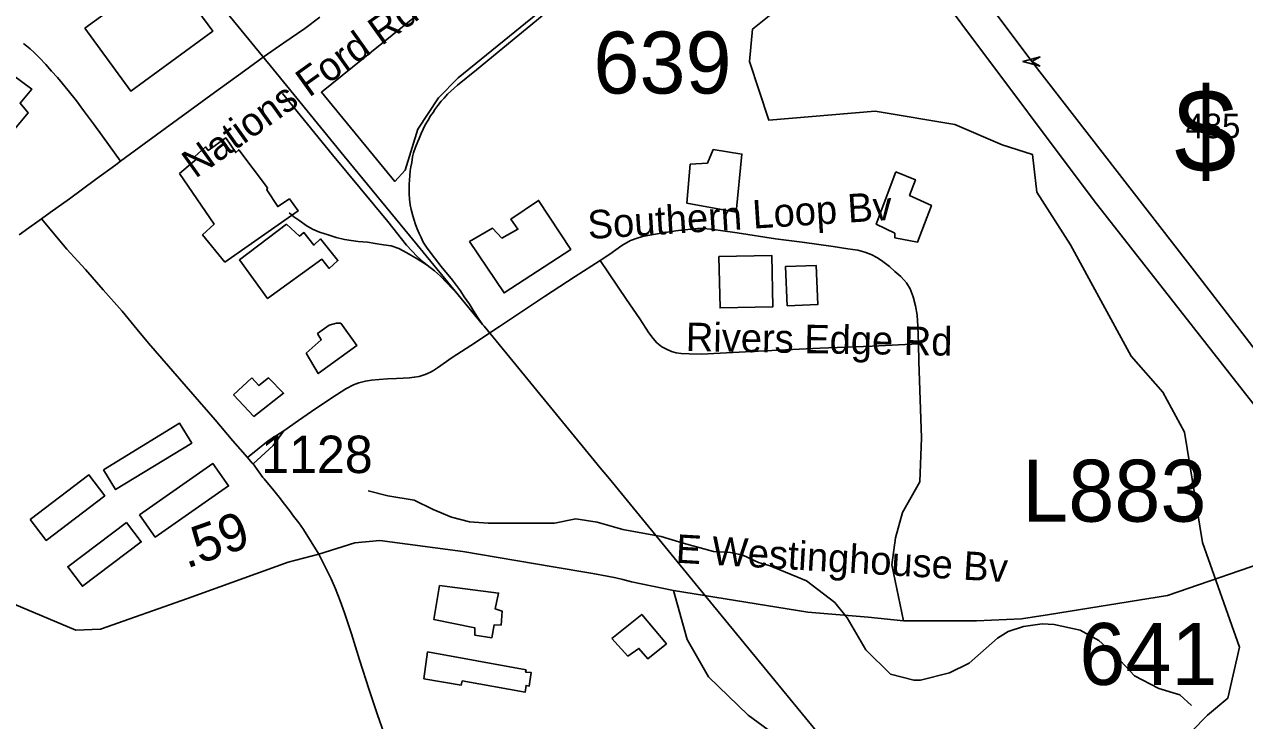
# Model space of a CAD drawing. Extents: x 1383679 to 1536984, y 460658 to 651027.
# Drawn here: x 1428024 to 1432096, y 500259 to 502583 of the extents above; entities that cross this region are included whole.
import ezdxf

# ---------------------------------------------------------------- set-up
doc = ezdxf.new("R2010")
doc.units = 0
for name, color, linetype in [('Default', 7, 'Continuous'), ('Exist Cultural Warehouse Building Footprint', 7, 'Continuous'), ('Exist Hydrographic Creek Single Shore', 7, 'Continuous'), ('Exist Hydrographic Misc Water Feature', 7, 'Continuous'), ('Exist Railroad Mainline', 7, 'Continuous'), ('Exist Railroad Spur', 7, 'Continuous'), ('Exist Road Non-System Type 51', 7, 'Continuous'), ('Exist Road Non-System Type 51 Label', 7, 'Continuous'), ('Exist Road Primary Interstate Divided Center Attributed', 7, 'Continuous'), ('Exist Road Primary Interstate Shield CELL', 7, 'Continuous'), ('Exist Road Primary Interstate Structure Cantilever Sign Attributed CELL', 7, 'Continuous'), ('Exist Road Primary Interstate Structure Cantilever Sign Number Label', 7, 'Continuous'), ('Exist Road Secondary Mileage Hundredths English Label', 7, 'Continuous'), ('Exist Road Secondary Structure Standard Bridge Number Label', 7, 'Continuous'), ('Exist Road Secondary Type 51 Attributed', 7, 'Continuous'), ('Exist Road Secondary Type 51 Label', 7, 'Continuous'), ('Exist Road Secondary Type 51 Number Label', 7, 'Continuous')]:
    doc.layers.add(name, color=color, linetype=linetype)

msp = doc.modelspace()

# ---------------------------------------------------------------- linework, layer by layer
at = {"layer": 'Exist Cultural Warehouse Building Footprint'}
for points in [[(1429889.4, 503063.1), (1430035.1, 502866.1), (1429755.2, 502635.5), (1429471.6, 502404.9), (1429406.4, 502338), (1429337.4, 502233.9), (1429295.2, 502096.3), (1429260.7, 502059.1), (1429015.4, 502356.6), (1429889.4, 503063.1)], [(1428226.1, 502571.1), (1428500, 502770.3), (1428653, 502560.1), (1428379.1, 502360.8), (1428226.1, 502571.1)], [(1427701.3, 502231.5), (1427863, 502081.6), (1428036.9, 502287.7), (1428010.3, 502320.5), (1428049, 502367.3), (1427954.8, 502437.6), (1427925.8, 502397.8), (1427879.9, 502432.9), (1427701.3, 502231.5)], [(1428541.5, 502085.1), (1428599.5, 502134.3), (1428592.2, 502141.3), (1428628.5, 502174.1), (1428638.1, 502162.4), (1428696.1, 502204.5), (1428729.9, 502155.3), (1428739.5, 502164.7), (1428836.1, 502038.2), (1428833.7, 502031.2), (1428869.9, 501975), (1428908.6, 502000.7), (1428937.5, 501960.9), (1428693.7, 501789.9), (1428618.8, 501881.3), (1428657.4, 501916.4), (1428541.5, 502085.1)], [(1430245.9, 502116.7), (1430234.4, 501986.6), (1430399.2, 501956.8), (1430418.4, 502150.2), (1430322.6, 502165.1), (1430303.4, 502120.5), (1430245.9, 502116.7)], [(1430932, 502090.7), (1430866.9, 501915.9), (1430928.2, 501886.2), (1430928.2, 501871.3), (1431004.9, 501856.4), (1431050.9, 501979.1), (1430978, 502012.6), (1430997.2, 502064.7), (1430932, 502090.7)], [(1429617.2, 501869.4), (1429670.9, 501899.2), (1429647.9, 501932.7), (1429739.9, 501995.9), (1429847.2, 501832.3), (1429624.9, 501687.2), (1429509.9, 501858.3), (1429586.6, 501902.9), (1429617.2, 501869.4)], [(1428898.9, 501916.4), (1428741.9, 501796.9), (1428836.1, 501668.1), (1429017.2, 501799.3), (1429041.4, 501768.8), (1429070.3, 501794.6), (1429012.4, 501867.2), (1428990.7, 501846.1), (1428956.8, 501888.3), (1428942.4, 501876.6), (1428898.9, 501916.4)], [(1430341.7, 501808.1), (1430517.8, 501812.3), (1430521.9, 501640.7), (1430345.8, 501636.6), (1430341.7, 501808.1)], [(1430564, 501774.6), (1430665.9, 501778.9), (1430671.4, 501648.2), (1430569.6, 501643.9), (1430564, 501774.6)], [(1428964.1, 501485.4), (1429005.1, 501417.5), (1429133.1, 501511.2), (1429080, 501586.1), (1429065.5, 501586.1), (1429041.4, 501579.1), (1429002.7, 501551), (1429014.8, 501529.9), (1428964.1, 501485.4)], [(1428783, 501403.4), (1428807.1, 501377.7), (1428838.5, 501403.4), (1428889.2, 501351.9), (1428790.2, 501274.6), (1428722.6, 501347.2), (1428783, 501403.4)], [(1428288, 501096.6), (1428328.5, 501030.3), (1428582.6, 501185.6), (1428542.1, 501251.8), (1428288, 501096.6)], [(1428408.7, 500946.7), (1428461, 500871.8), (1428705.7, 501042.7), (1428653.5, 501117.5), (1428408.7, 500946.7)], [(1428044.1, 500930.3), (1428097.3, 500860.6), (1428292.8, 501009.9), (1428239.6, 501079.6), (1428044.1, 500930.3)], [(1428365.3, 500920.9), (1428414.4, 500855.7), (1428218, 500707.7), (1428168.9, 500772.9), (1428365.3, 500920.9)], [(1429409.6, 500710.7), (1429390.3, 500597.1), (1429527.9, 500568.9), (1429527.9, 500544.3), (1429584.6, 500536.2), (1429591.9, 500579.5), (1429614.8, 500578.3), (1429618.4, 500625.2), (1429595.5, 500632.2), (1429606.4, 500684.9), (1429409.6, 500710.7)], [(1429984.3, 500533.2), (1430037.4, 500474.7), (1430074.8, 500500.4), (1430105, 500465.3), (1430166.6, 500515.7), (1430084.5, 500614), (1429984.3, 500533.2)], [(1429369.7, 500489.3), (1429357.7, 500399.1), (1429482, 500378), (1429485.6, 500392.1), (1429695.7, 500354.6), (1429698.1, 500376.9), (1429709, 500374.5), (1429715, 500420.2), (1429696.9, 500421.4), (1429698.1, 500428.4), (1429369.7, 500489.3)]]:
    msp.add_lwpolyline(points, dxfattribs=at)
at = {"layer": 'Exist Hydrographic Creek Single Shore'}
msp.add_lwpolyline([(1431863.8, 500167), (1431971.5, 500277.6), (1432039.5, 500334.3), (1432079.1, 500504.5), (1431955.3, 500853.6), (1431895.3, 501222.4), (1431823.3, 501355.2), (1431717.3, 501475.5), (1431515.3, 501847.2), (1431402.3, 502023.4), (1431388.3, 502148.4), (1431286.8, 502181.7), (1431128.8, 502248.9), (1430862.9, 502293.6), (1430508, 502263.9), (1430444.3, 502459.5), (1430454.3, 502567.7), (1430525.8, 502625)], dxfattribs=at)
at = {"layer": 'Exist Hydrographic Misc Water Feature'}
msp.add_lwpolyline([(1431918.9, 500310.3), (1431879.5, 500345.5), (1431810, 500366.7), (1431728.8, 500408.5), (1431666.1, 500475.4), (1431609, 500526.6), (1431547.6, 500561.5), (1431460, 500579.7), (1431420, 500582.1), (1431357.9, 500573.5), (1431307.4, 500556.5), (1431271, 500535.1), (1431177.3, 500450.8), (1431110.7, 500418.5), (1431014.1, 500394.2), (1430992.2, 500394.6), (1430914.4, 500414.2), (1430832, 500495.5), (1430770.1, 500602.6), (1430729, 500653.5), (1430634.4, 500726), (1430513.3, 500776), (1430473.5, 500786.6), (1430422, 500811.5), (1430380.1, 500820.5), (1430324.2, 500824.1), (1430222.7, 500851.6), (1430149.1, 500873.6), (1430021.4, 500897.5), (1429935.8, 500921.4), (1429864.1, 500932.7), (1429793.7, 500918.5), (1429667.7, 500918.6), (1429571.7, 500918.9), (1429509.8, 500923.4), (1429450, 500938.5), (1429388.4, 500964.4), (1429325.1, 500995.2), (1429237.3, 501009.3), (1429171.6, 501026.2)], dxfattribs=at)
at = {"layer": 'Exist Railroad Mainline'}
msp.add_line((1429471.2, 501680.4), (1429553.1, 501582), dxfattribs=at)
for points in [[(1428232.5, 503192.9), (1428285.2, 503130.3), (1428411.9, 502975.2), (1428523.5, 502837.8), (1428676.4, 502650.7), (1428854.3, 502434), (1429091.6, 502143.9), (1429309, 501878.8), (1429471.2, 501680.4)], [(1429553.1, 501582), (1429558.3, 501575.8), (1429946, 501102.8), (1429976.2, 501066), (1430262.6, 500717.3), (1430503.1, 500424.9), (1430759, 500113.1), (1430980.7, 499842.6), (1431197.3, 499578.5), (1431313.2, 499442.3), (1431408.4, 499341.6), (1431509.9, 499247.1), (1431598.4, 499173.4), (1431681.4, 499111.8), (1431793, 499036.9), (1431931.8, 498956.2), (1432066.4, 498888.7), (1432075, 498884.6), (1432222.4, 498814.6)]]:
    msp.add_lwpolyline(points, dxfattribs=at)
at = {"layer": 'Exist Railroad Spur'}
for points in [[(1429553.1, 501582), (1429534.3, 501609.8), (1429520.1, 501632.4), (1429509.5, 501649.1), (1429500.6, 501662.1), (1429492.2, 501674.2), (1429479, 501694), (1429452.7, 501729), (1429415.1, 501775.1), (1429381.6, 501818.3), (1429366.2, 501839.5), (1429355.4, 501856.8), (1429347.8, 501871.4), (1429341.6, 501885.1), (1429334.5, 501900.4), (1429329, 501914.9), (1429323.4, 501932.8), (1429319.1, 501948.6), (1429315, 501965.9), (1429312, 501981), (1429309.8, 501999.6), (1429308.1, 502017.8), (1429308.1, 502030.9), (1429307.7, 502048.6), (1429309.2, 502064.8), (1429310.2, 502077.2), (1429311.5, 502094.5), (1429313.5, 502107.6), (1429317.2, 502122.3), (1429319.7, 502141.1), (1429323.2, 502154.3), (1429329.5, 502173.6), (1429336.8, 502192.1), (1429341.4, 502201.9), (1429347.9, 502218.5), (1429354.5, 502233.8), (1429361.7, 502248.5), (1429371.2, 502263.5), (1429379.2, 502277.7), (1429387.8, 502289), (1429394.3, 502298.9), (1429403.6, 502312.9), (1429415.3, 502326.5), (1429424.8, 502336.9), (1429436.2, 502350.5), (1429447, 502360), (1429470, 502380.6), (1429532.4, 502431.3), (1429620.6, 502504), (1429751.9, 502611.3)], [(1429471.2, 501680.4), (1429412.9, 501743.3), (1429392.8, 501760.8), (1429368, 501779.4), (1429355.7, 501789.6), (1429335, 501809), (1429299.5, 501846.6), (1429237.6, 501925.3), (1429052.9, 502147.6), (1428885.8, 502352.9)], [(1429368, 501779.4), (1429334.5, 501800.9), (1429300.1, 501821.1), (1429274.2, 501835.2), (1429248.7, 501843.6), (1429222.7, 501847.9), (1429195.3, 501852.2), (1429169.6, 501856.3), (1429138.2, 501858.9), (1429114.9, 501861.5), (1429092.9, 501865.4), (1429064.8, 501871.5), (1429037.7, 501880.5), (1429009.4, 501890), (1428985.7, 501900.2), (1428965.1, 501911.8), (1428943.5, 501927.2), (1428923.9, 501940.6), (1428907.9, 501954.2)]]:
    msp.add_lwpolyline(points, dxfattribs=at)
at = {"layer": 'Exist Road Non-System Type 51'}
for points in [[(1428345.5, 502126.8), (1428285.1, 502209.6), (1428255, 502251.1), (1428221.4, 502295.4), (1428198.2, 502328.3), (1428171, 502362), (1428150.2, 502387.5), (1428134.7, 502405.9), (1428115.2, 502427.5), (1428096.4, 502449.1), (1428075.1, 502472), (1428057.5, 502489.3), (1428043.3, 502501.4), (1428021.7, 502519.7)], [(1428081.4, 501934.5), (1428166.2, 501832.7), (1428203, 501793.1), (1428228.5, 501765.6), (1428287.4, 501697.6), (1428350.3, 501625.8), (1428400.4, 501564.3), (1428438.5, 501519), (1428585.9, 501349.4), (1428661.3, 501263.1), (1428719.7, 501193.3), (1428768.9, 501137.3)], [(1429945.1, 501795.4), (1429978.2, 501816.8), (1430018.4, 501845.5), (1430046.3, 501861.9), (1430068.8, 501870.1), (1430086.3, 501875.6), (1430111.5, 501880.1), (1430149.6, 501886.6), (1430198.4, 501893.9), (1430225.4, 501897.8), (1430251.6, 501900.2), (1430270.2, 501902.4), (1430290.3, 501901.7), (1430314, 501899.5), (1430347.1, 501894.8), (1430402.2, 501887.4), (1430530.1, 501868), (1430619.1, 501856.1), (1430722.7, 501841.6), (1430771.5, 501833.9), (1430805.2, 501829.7), (1430828.8, 501823.5), (1430850.1, 501814.8), (1430870.7, 501804), (1430888.6, 501792.1), (1430911.3, 501774.9), (1430929.2, 501758.8), (1430949.3, 501741.3), (1430967.9, 501720.8), (1430980.2, 501700.1), (1430990.2, 501674.2), (1430998.2, 501643.9), (1431003.4, 501612.3), (1431005.5, 501575.4), (1431007.3, 501516.8)], [(1428890.2, 501226.4), (1428938.8, 501260.6), (1428982.7, 501290.6), (1429023.5, 501319.3), (1429065.9, 501346.6), (1429097, 501366.7), (1429122.5, 501380.1), (1429139.8, 501387), (1429162.2, 501392.8), (1429182.3, 501395.4), (1429207.8, 501397.5), (1429236.3, 501399.9), (1429266, 501401.2), (1429288.6, 501401.9), (1429309.2, 501403), (1429325, 501405.3), (1429341.6, 501408.4), (1429352, 501411.6), (1429361.9, 501414.6), (1429369.9, 501417.7), (1429379.6, 501422.4), (1429389.3, 501427.8), (1429403.2, 501436.7), (1429452, 501471.2), (1429514, 501511.2), (1429609.6, 501574.7), (1429760, 501675), (1429861.7, 501741.3), (1429945.1, 501795.4)], [(1431007.3, 501516.8), (1430852.9, 501509.3), (1430678.8, 501502.4), (1430472.4, 501492.6), (1430345.6, 501486.2), (1430283.6, 501482.7), (1430242.5, 501483.3), (1430215.9, 501484.9), (1430199, 501487.2), (1430183.3, 501491.6), (1430166.9, 501498.7), (1430151.3, 501507.1), (1430135.1, 501519.8), (1430122.5, 501534.3), (1430108.3, 501554), (1430078.2, 501600.9), (1430033.5, 501665.1), (1429945.1, 501795.4)], [(1431007.3, 501516.8), (1431009.2, 501457.6), (1431017.4, 501203.1), (1431011.7, 501056.5), (1430954.6, 500954.4), (1430930.5, 500869.9), (1430918.5, 500779.4), (1430957.6, 500592.7)], [(1428768.9, 501137.3), (1428837.7, 501192.7), (1428890.2, 501226.4)], [(1428890.2, 501226.4), (1428854.3, 501177.1), (1428787.3, 501115.9)], [(1428768.9, 501137.3), (1428784.9, 501119.2), (1428787.3, 501115.9)], [(1428787.3, 501115.9), (1428819.5, 501071.3), (1428823.9, 501066), (1428856.9, 501027.5), (1428874.5, 501005.3), (1428892.5, 500981.3), (1428909.2, 500960.4), (1428922.4, 500942), (1428940, 500919.3), (1428955.4, 500896.9), (1429006.3, 500814.4)], [(1429223.8, 500218.8), (1429202.9, 500279.2), (1429175.2, 500362.4), (1429142.8, 500462.5), (1429115.5, 500548.5), (1429092, 500618.9), (1429078.4, 500658.7), (1429062.8, 500699.3), (1429047.7, 500732.2), (1429006.3, 500814.4)], [(1430957.6, 500592.7), (1431201.1, 500592.7), (1431351.4, 500598.6), (1431444.6, 500613.2), (1431838.5, 500677.3), (1432220.3, 500808.6)], [(1430190.6, 500694.2), (1430235.8, 500529.6), (1430307.4, 500405.3), (1430439.4, 500277.3), (1430639.1, 500131), (1430814, 499893.8), (1431018.6, 499651.2), (1431314.4, 499288.5), (1431549.9, 498991), (1431717.4, 498793.3), (1431720, 498790.1)], [(1430190.6, 500694.2), (1430638.9, 500621.9), (1430840.3, 500604.4), (1430957.6, 500592.7)]]:
    msp.add_lwpolyline(points, dxfattribs=at)
at = {"layer": 'Exist Road Primary Interstate Divided Center Attributed'}
for points in [[(1432558.9, 500937.5), (1432485.7, 501036.1), (1431955, 501724.9), (1431385.7, 502459), (1430945.6, 503049.2)], [(1430895.9, 502932.5), (1431152.5, 502584.2), (1431594.1, 501994.5), (1432135.5, 501303.3), (1432336.5, 501039.7), (1432444.6, 500897.6)]]:
    msp.add_lwpolyline(points, dxfattribs=at)
at = {"layer": 'Exist Road Primary Interstate Structure Cantilever Sign Attributed CELL'}
msp.add_lwpolyline([(1431413.4, 502443.6), (1431356, 502459), (1431413.4, 502474.4), (1431385.7, 502459)], close=True, dxfattribs=at)
at = {"layer": 'Exist Road Secondary Type 51 Attributed'}
for points in [[(1429010.3, 502607.6), (1428959.7, 502570), (1428890.5, 502521.5), (1428821.5, 502474)], [(1428821.5, 502474), (1428758.3, 502428.5), (1428658.7, 502356.1), (1428534.9, 502266.2), (1428424.2, 502184.3), (1428345.5, 502126.8), (1428329, 502114.8), (1428261.3, 502065.5), (1428174.4, 502001.5), (1428110.7, 501955.5), (1428081.4, 501934.5), (1428066, 501923.5), (1428039.2, 501904.5), (1428006.5, 501881.2)], [(1430190.6, 500694.2), (1430050.4, 500722.8), (1430021.6, 500729.9), (1429997.3, 500735.4), (1429969.1, 500741.2), (1429920.9, 500750.4), (1429788.9, 500772.6), (1429486.8, 500823.6), (1429210.8, 500861.1), (1429126.6, 500852.4), (1429006.3, 500814.4), (1428904.1, 500788.2), (1428568.7, 500667.5), (1428278.4, 500565.1), (1428195.5, 500561.4), (1427223.8, 500970.2)]]:
    msp.add_lwpolyline(points, dxfattribs=at)

# ---------------------------------------------------------------- texts
at = {"layer": 'Default'}
msp.add_text('$', height=278.9, dxfattribs=at).set_placement((1431861.3, 502088.4))
at = {"layer": 'Exist Road Non-System Type 51 Label'}
for s, rotation, p in [('Southern Loop Bv', 3.6244, (1429906.6, 501866.6)), ('Rivers Edge Rd', 358.9894, (1430230.7, 501493)), ('E Westinghouse Bv', 356.6221, (1430196.3, 500786.7))]:
    msp.add_text(s, height=95, rotation=rotation, dxfattribs=at).set_placement(p)
at = {"layer": 'Exist Road Primary Interstate Shield CELL'}
msp.add_text('485', height=82.02, dxfattribs=at).set_placement((1431898.6, 502203.2))
at = {"layer": 'Exist Road Primary Interstate Structure Cantilever Sign Number Label'}
msp.add_text('L883', height=206.69, dxfattribs=at).set_placement((1431353.6, 500923.4))
at = {"layer": 'Exist Road Secondary Mileage Hundredths English Label'}
msp.add_text('.59', height=125, rotation=19.4342, dxfattribs=at).set_placement((1428566, 500766.3))
at = {"layer": 'Exist Road Secondary Structure Standard Bridge Number Label'}
for s, p in [('639', (1429922.9, 502352.4)), ('641', (1431544.3, 500378.5))]:
    msp.add_text(s, height=206.69, dxfattribs=at).set_placement(p)
at = {"layer": 'Exist Road Secondary Type 51 Label'}
msp.add_text('Nations Ford Rd', height=95, rotation=35.4885, dxfattribs=at).set_placement((1428594.7, 502067.2))
at = {"layer": 'Exist Road Secondary Type 51 Number Label'}
msp.add_text('1128', height=125, dxfattribs=at).set_placement((1428814.7, 501085.6))

doc.saveas('drawing.dxf')
